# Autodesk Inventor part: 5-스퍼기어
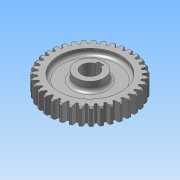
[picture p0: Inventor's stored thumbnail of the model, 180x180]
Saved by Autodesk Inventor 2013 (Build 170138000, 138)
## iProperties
Created: 2013-08
Part Number: 5-스퍼기어
Material: 강
Document SubType Name: Modeling
Designer: 한국산업디자인학원
Categories: <?xml version="1.0" encoding="UTF-16"?> <MemberInstance><Categories><FamilyTemplate><FamilyTemplateParameter ValueType="xs:double" Id="1" ObjectReferenceKey="da
Density: 1 g/cm^3
CustomPartVersion: 1
Author: 한국산업디자인학원
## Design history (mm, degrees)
sketch "Sketch1"
  geometry: C1 r 37 at (0, 0)
  constraints: 1 centre point
  dimensions: "d0" = 74 diameter of C1 (= da_da)
extrude "Extrusion1" new body sketch "Sketch1" distance "d1" = 15 (= da_b); taper "d2" = 0 deg
chamfer "모따기1" distance "d49" = 1; stored, may be unused: second distance "d50" = 2, angle "d51" = 45 deg
node "작업 평면11"
sketch "스케치3"
  geometry: L1 (-2.5, 7.071)-(-2.5, 9.8); L2 (-2.5, 9.8)-(2.5, 9.8); L3 (2.5, 9.8)-(2.5, 7.071); C1 r 12.5 at (0, 0); A1 r 7.5 centre (0, 0) between (-2.5, 7.071) and (2.5, 7.071); 2 further points
  constraints: 6 end point, 2 centre point, 2 coincident, 2 point on circle, 1 midpoint, 1 parallel, 1 perpendicular, 1 vertical, 1 vertical alignment
  dimensions: "d53" = 25 diameter of C1; "d55" = 15 diameter of A1; "d56" = 5 distance of L1.end L2.end; "d57" = 17.3 dimension on A1 L2
extrude "돌출2" join sketch "스케치3" distance "d58" = 31; taper "d59" = 0 deg
extrude "돌출3" cut sketch "스케치3" distance "d60" = 31; taper "d61" = 0 deg
sketch "스케치4"
  geometry: C1 r 12.5 at (0, 0) reference; C2 r 27.5 at (0, 0)
  constraints: 1 centre point, 1 coincident
  dimensions: "d62" = 55 diameter of C2
extrude "돌출4" cut sketch "스케치4" distance "d64" = 5; taper "d65" = 0 deg
node "작업 평면12"
fillet "모깎기1" dims "d66" = 3
workplane "Work Plane2"
feature "피치 지름" dims "d4" = 10, "d5" = 0
workplane "Work Plane8"
workplane "Work Plane9"
feature "스퍼 기어" dims "da_b" = 15, "da_d" = 70, "da_aw" = 70, "da_da" = 74, "da_df" = 65, "da_dw" = 70, angle "da_beta" = 0 deg, "da_lefttooth" = 0, "da_righttooth" = 0
body "Solid1"
mirror "대칭1"
sketch "Sketch2"
  geometry: C1 r 37 at (0, 0) reference; C2 r 35 at (0, 0)
  constraints: 1 centre point, 1 coincident
  dimensions: "d3" = 70 diameter of C2 (= da_dw)
body "Srf1"
other parameters: "d17" = 0, "d34" = 0.8976 (computed from da_z), "d39" = 0, "d41" = 0, "d47" = 0, "d48" = 0, "d52" = 3
